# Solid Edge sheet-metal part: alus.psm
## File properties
Author: Romil
Template: iso sheet metal.psm
Last saved by: Romil
Revision: 9
Application: Solid Edge
Accuracy: 0.990
Material Thickness: 1.00 mm
Bend Radius: 1.00 mm
Relief Width: 1.00 mm
Relief Length: 0.00 mm
Neutral Factor: 0.330
Minimum Arc Length: 0.10 mm
Deviational Tolerance: 0.10 mm
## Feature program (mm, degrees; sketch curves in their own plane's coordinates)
base tab "unnamed BaseTab 1"
jog tab "JogTab_1"  OffsetDistance = 10 mm
mirror "unnamed Mirror 1" of "JogTab_1" about plane through (0, 0, 0) normal (1, 0, 0)
jog tab "unnamed JogTab 1"
flange "Flange_2"
dimple "Dimple_1"
mirror "unnamed Mirror 2" of "Dimple_1" about plane through (0, 0, 0) normal (1, 0, 0)
dimple "unnamed Dimple 1"
louver "Louver_2"  LouverDepth = 5 mm; LouverHeight = 2 mm
pattern "unnamed Pattern 1" of "Louver_2"
louver "unnamed Louver 1"
louver "unnamed Louver 2"
louver "unnamed Louver 3"
louver "unnamed Louver 4"
louver "unnamed Louver 5"
louver "unnamed Louver 6"
louver "unnamed Louver 7"
flange "Flange_3"
hem "Hem_2"
bead "unnamed Bead 1"
sketch used by "ExtrudedCutout_1" plane through (51.1585, -131.9198, -39.2063) normal (0.520259, -0.854008, 0) x-axis (0.854008, 0.520259, 0)
extrude "ExtrudedCutout_1" cut
bead "unnamed Bead 2"
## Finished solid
Body 1: solid body, 365 faces, 932 edges, 584 vertices, 9 separate solids.
  Faces by surface: plane 182, cylinder 62, swept 41, sphere 32, cone 20, torus 20, spline 8
  Edges by curve: line 582, circle 240, spline 82, curve on surface 16, ellipse 12
Bounding box of the edges (mm; curved faces can reach further): 153.576 x 205.571 x 12.250, from (-76.7881, -147.7331, -45.2063) to (76.7881, 57.8381, -32.9563).
Cylindrical faces by radius (mm): R0.002 x1, R1 x38, R1.002 x1, R2 x6, R6.25 x8, R7.25 x8
Conical faces (half-angle, radius in mm at the cone's reference point): 15 deg R0.3014 x2, 15 deg R0.6363 x2, 15 deg R1.2673 x2, 15 deg R1.6023 x2, 15 deg R12.9375 x2, 15 deg R13.9034 x2, 15 deg R14.8411 x2, 15 deg R15.807 x2, 15 deg R24.3385 x1, 15 deg R25.3044 x1, 15 deg R26.2422 x1, 15 deg R27.2081 x1
Toroidal faces (ring radius, tube radius in mm): R0.5 r1 x4, R1.6023 r1 x4, R12.9375 r1 x2, R14.0397 r1 x2, R15.0397 r1 x2, R16.142 r1 x2, R24.3385 r1 x1, R25.4408 r1 x1, R26.4408 r1 x1, R27.543 r1 x1
Spherical faces by radius (mm): R6.25 x16, R7.25 x16
Planar faces by outward normal: +x 3, +y 10, +z 33, -x 3, -y 12, -z 28, oblique 93
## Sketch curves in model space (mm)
spline (69.9628, -120.4643, -40.5603) -> (70.6542, -120.0431, -40.5603) -> (71.3456, -119.6219, -40.5603)
spline (69.5461, -120.7181, -38.5998) -> (71.3144, -119.6409, -38.329) -> (69.9628, -120.4643, -40.5603)
spline (69.9011, -120.5018, -38.6457) -> (69.7236, -120.61, -38.6227) -> (69.5461, -120.7181, -38.5998)
spline (69.4788, -120.7591, -40.9454) -> (70.946, -119.8653, -38.7796) -> (69.9011, -120.5018, -38.6457)
spline (71.3456, -119.6219, -40.9454) -> (70.4122, -120.1905, -40.9454) -> (69.4788, -120.7591, -40.9454)
spline (71.3456, -119.6219, -40.5603) -> (71.3456, -119.6219, -40.7529) -> (71.3456, -119.6219, -40.9454)
spline (68.6491, -121.2646, -37.6501) -> (68.6491, -121.2646, -39.2978) -> (68.6491, -121.2646, -40.9454)
spline (68.4268, -121.4, -37.6501) -> (68.5379, -121.3323, -37.6501) -> (68.6491, -121.2646, -37.6501)
spline (67.6139, -121.8952, -38.475) -> (68.0774, -121.6129, -38.1335) -> (68.4268, -121.4, -37.6501)
spline (67.6139, -121.8952, -38.8645) -> (67.6139, -121.8952, -38.6698) -> (67.6139, -121.8952, -38.475)
spline (68.3053, -121.474, -38.3788) -> (67.9783, -121.6732, -38.6567) -> (67.6139, -121.8952, -38.8645)
spline (68.3053, -121.474, -40.9454) -> (68.3053, -121.474, -39.6621) -> (68.3053, -121.474, -38.3788)
spline (68.6491, -121.2646, -40.9454) -> (68.4772, -121.3693, -40.9454) -> (68.3053, -121.474, -40.9454)
closed spline through (65.5247, -123.1679, -39.3262), (66.0846, -122.8269, -40.6675), (66.6383, -122.4896, -39.6153), (66.0705, -122.8354, -37.9828)
closed spline through (65.1678, -123.3854, -39.3262), (66.1581, -122.7821, -37.6533), (66.9978, -122.2705, -39.5223), (65.8508, -122.9693, -40.9685)
spline (63.415, -124.4532, -40.5603) -> (64.1064, -124.032, -40.5603) -> (64.7978, -123.6108, -40.5603)
spline (62.9983, -124.707, -38.5998) -> (64.7526, -123.6383, -38.2677) -> (63.415, -124.4532, -40.5603)
spline (63.3552, -124.4896, -38.6457) -> (63.1767, -124.5983, -38.6227) -> (62.9983, -124.707, -38.5998)
spline (62.9329, -124.7469, -40.9454) -> (64.2743, -123.9297, -39.043) -> (63.3552, -124.4896, -38.6457)
spline (64.7978, -123.6108, -40.9454) -> (63.8653, -124.1788, -40.9454) -> (62.9329, -124.7469, -40.9454)
spline (64.7978, -123.6108, -40.5603) -> (64.7978, -123.6108, -40.7529) -> (64.7978, -123.6108, -40.9454)
spline (60.9147, -125.9763, -40.9454) -> (60.7493, -126.0771, -40.9454) -> (60.584, -126.1778, -40.9454)
spline (61.6809, -125.5096, -38.5604) -> (61.2978, -125.743, -39.7529) -> (60.9147, -125.9763, -40.9454)
spline (61.3258, -125.7259, -38.5604) -> (61.5033, -125.6178, -38.5604) -> (61.6809, -125.5096, -38.5604)
spline (60.7465, -126.0788, -40.4706) -> (61.0302, -125.906, -39.5131) -> (61.3258, -125.7259, -38.5604)
spline (60.1803, -126.4237, -38.5604) -> (60.4705, -126.2469, -39.5127) -> (60.7465, -126.0788, -40.4706)
spline (59.8141, -126.6469, -38.5604) -> (59.9972, -126.5353, -38.5604) -> (60.1803, -126.4237, -38.5604)
spline (60.584, -126.1778, -40.9454) -> (60.199, -126.4123, -39.7529) -> (59.8141, -126.6469, -38.5604)
closed spline through (58.0743, -127.7067, -39.7529), (58.6698, -127.3439, -40.6675), (59.2664, -126.9805, -39.7657), (58.6698, -127.3439, -38.8383)
closed spline through (57.7174, -127.9241, -39.7529), (58.6792, -127.3382, -38.5079), (59.6227, -126.7634, -39.7914), (58.6489, -127.3567, -40.9999)
spline (56.2244, -128.8337, -40.9454) -> (56.0534, -128.9379, -40.9454) -> (55.8824, -129.042, -40.9454)
spline (56.2244, -128.8337, -40.0024) -> (56.2244, -128.8337, -40.4739) -> (56.2244, -128.8337, -40.9454)
spline (56.4636, -128.688, -39.731) -> (56.344, -128.7608, -39.8667) -> (56.2244, -128.8337, -40.0024)
spline (57.1475, -128.2713, -40.9454) -> (56.8055, -128.4797, -40.3382) -> (56.4636, -128.688, -39.731)
spline (57.5735, -128.0118, -40.9454) -> (57.3605, -128.1416, -40.9454) -> (57.1475, -128.2713, -40.9454)
spline (56.7121, -128.5366, -39.4488) -> (57.1428, -128.2742, -40.1971) -> (57.5735, -128.0118, -40.9454)
spline (57.4932, -128.0607, -38.5604) -> (57.1026, -128.2987, -39.0046) -> (56.7121, -128.5366, -39.4488)
spline (57.0466, -128.3328, -38.5604) -> (57.2699, -128.1968, -38.5604) -> (57.4932, -128.0607, -38.5604)
spline (56.2244, -128.8337, -39.5275) -> (56.6355, -128.5833, -39.044) -> (57.0466, -128.3328, -38.5604)
spline (56.2244, -128.8337, -37.6589) -> (56.2244, -128.8337, -38.5932) -> (56.2244, -128.8337, -39.5275)
spline (55.8824, -129.042, -37.6589) -> (56.0534, -128.9379, -37.6589) -> (56.2244, -128.8337, -37.6589)
spline (55.8824, -129.042, -40.9454) -> (55.8824, -129.042, -39.3022) -> (55.8824, -129.042, -37.6589)
spline (54.0399, -130.1645, -40.9454) -> (53.868, -130.2692, -40.9454) -> (53.6961, -130.3739, -40.9454)
spline (55.0079, -129.5748, -40.9454) -> (54.5491, -129.8542, -38.8539) -> (54.0399, -130.1645, -40.9454)
spline (55.3517, -129.3653, -40.9454) -> (55.1798, -129.4701, -40.9454) -> (55.0079, -129.5748, -40.9454)
spline (54.0063, -130.185, -38.8995) -> (55.3195, -129.385, -39.0302) -> (55.3517, -129.3653, -40.9454)
spline (54.0063, -130.185, -38.5604) -> (54.0063, -130.185, -38.73) -> (54.0063, -130.185, -38.8995)
spline (53.6961, -130.3739, -38.5604) -> (53.8512, -130.2794, -38.5604) -> (54.0063, -130.185, -38.5604)
spline (53.6961, -130.3739, -40.9454) -> (53.6961, -130.3739, -39.7529) -> (53.6961, -130.3739, -38.5604)
spline (52.9112, -130.8521, -39.5253) -> (52.3485, -131.1948, -38.8382) -> (51.7769, -131.5431, -39.5253)
spline (51.7769, -131.5431, -39.5253) -> (52.3441, -131.1976, -39.5253) -> (52.9112, -130.8521, -39.5253)
spline (51.7582, -131.5544, -39.8579) -> (52.2206, -131.2728, -40.6481) -> (52.9075, -130.8543, -40.1752)
spline (53.2719, -130.6323, -39.8579) -> (52.5151, -131.0934, -39.8579) -> (51.7582, -131.5544, -39.8579)
spline (53.2625, -130.638, -40.2277) -> (51.4188, -131.7612, -39.4833) -> (53.2719, -130.6323, -39.8579)
spline (52.9075, -130.8543, -40.1752) -> (53.085, -130.7462, -40.2015) -> (53.2625, -130.638, -40.2277)
spline (50.0466, -132.5972, -37.6436) -> (50.1503, -132.534, -37.8317) -> (50.254, -132.4708, -38.0199)
spline (49.6523, -132.8374, -37.6436) -> (49.8494, -132.7173, -37.6436) -> (50.0466, -132.5972, -37.6436)
spline (50.0634, -132.587, -38.2672) -> (49.8578, -132.7122, -37.9554) -> (49.6523, -132.8374, -37.6436)
spline (50.4259, -132.3661, -38.2672) -> (50.2446, -132.4765, -38.2672) -> (50.0634, -132.587, -38.2672)
spline (50.865, -132.0986, -37.6436) -> (50.6455, -132.2323, -37.9554) -> (50.4259, -132.3661, -38.2672)
spline (50.4689, -132.3399, -37.6436) -> (50.6669, -132.2193, -37.6436) -> (50.865, -132.0986, -37.6436)
spline (50.254, -132.4708, -38.0199) -> (50.3614, -132.4054, -37.8317) -> (50.4689, -132.3399, -37.6436)
spline (50.6894, -132.2056, -39.2321) -> (51.0377, -131.9934, -39.9281) -> (49.4112, -132.9842, -40.2277)
spline (51.0257, -132.0007, -39.1796) -> (50.8576, -132.1031, -39.2059) -> (50.6894, -132.2056, -39.2321)
spline (49.7532, -132.7759, -40.1752) -> (49.5555, -132.8963, -39.5323) -> (51.0257, -132.0007, -39.1796)
spline (49.4112, -132.9842, -40.2277) -> (49.5822, -132.8801, -40.2015) -> (49.7532, -132.7759, -40.1752)
spline (48.8637, -133.3178, -38.8777) -> (48.8637, -133.3178, -39.901) -> (49.2131, -133.1049, -40.5844)
spline (49.2131, -133.1049, -38.8777) -> (49.0384, -133.2114, -38.8777) -> (48.8637, -133.3178, -38.8777)
spline (49.2131, -133.1049, -38.5604) -> (49.2131, -133.1049, -38.719) -> (49.2131, -133.1049, -38.8777)
spline (48.8637, -133.3178, -38.5604) -> (49.0384, -133.2114, -38.5604) -> (49.2131, -133.1049, -38.5604)
spline (48.8637, -133.3178, -37.7289) -> (48.8637, -133.3178, -38.1446) -> (48.8637, -133.3178, -38.5604)
spline (48.5199, -133.5273, -37.9718) -> (48.6918, -133.4225, -37.8503) -> (48.8637, -133.3178, -37.7289)
spline (48.5199, -133.5273, -38.5604) -> (48.5199, -133.5273, -38.2661) -> (48.5199, -133.5273, -37.9718)
spline (48.2638, -133.6832, -38.5604) -> (48.3918, -133.6052, -38.5604) -> (48.5199, -133.5273, -38.5604)
spline (48.2638, -133.6832, -38.8777) -> (48.2638, -133.6832, -38.719) -> (48.2638, -133.6832, -38.5604)
spline (48.5199, -133.5273, -38.8777) -> (48.3918, -133.6052, -38.8777) -> (48.2638, -133.6832, -38.8777)
spline (49.2598, -133.0765, -40.9411) -> (48.5199, -133.5272, -40.2671) -> (48.5199, -133.5273, -38.8777)
spline (49.2131, -133.1049, -40.5844) -> (49.2365, -133.0907, -40.7627) -> (49.2598, -133.0765, -40.9411)
closed spline through (46.582, -134.7078, -39.7354), (47.1118, -134.385, -40.6675), (47.6891, -134.0333, -39.6786), (47.1539, -134.3594, -38.8385)
spline (46.5895, -134.7032, -40.6478) -> (46.5895, -134.7032, -40.7966) -> (46.5895, -134.7032, -40.9454)
spline (46.6157, -134.6873, -38.8273) -> (48.0371, -133.8214, -39.927) -> (46.5895, -134.7032, -40.6478)
spline (46.6157, -134.6873, -37.6589) -> (46.6157, -134.6873, -38.2431) -> (46.6157, -134.6873, -38.8273)
spline (46.2718, -134.8967, -37.6589) -> (46.4438, -134.792, -37.6589) -> (46.6157, -134.6873, -37.6589)
spline (46.2718, -134.8967, -40.9454) -> (46.2718, -134.8967, -39.3022) -> (46.2718, -134.8967, -37.6589)
spline (46.5895, -134.7032, -40.9454) -> (46.4307, -134.8, -40.9454) -> (46.2718, -134.8967, -40.9454)
spline (44.5527, -135.9441, -38.2759) -> (44.4237, -136.0226, -38.2759) -> (44.2948, -136.1012, -38.2759)
spline (45.5804, -135.3179, -37.7573) -> (45.1463, -135.5824, -38.2608) -> (44.5527, -135.9441, -38.2759)
spline (45.33, -135.4705, -37.7573) -> (45.4552, -135.3942, -37.7573) -> (45.5804, -135.3179, -37.7573)
spline (44.2948, -136.1012, -38.2759) -> (44.6748, -135.8697, -37.7662) -> (45.33, -135.4705, -37.7573)
closed spline through (44.3284, -136.0807, -39.7529), (44.9232, -135.7183, -40.6676), (45.5205, -135.3545, -39.7657), (44.9233, -135.7183, -38.8383)
closed spline through (43.9715, -136.2981, -39.7529), (44.9154, -135.7231, -38.5079), (45.8772, -135.1372, -39.7709), (44.8997, -135.7327, -40.9999)
spline (41.6899, -137.6881, -38.0199) -> (41.6899, -137.6881, -38.5648) -> (41.6899, -137.6881, -39.1096)
spline (41.6899, -137.6881, -39.1096) -> (43.1811, -136.7796, -38.5526) -> (41.6899, -137.6881, -38.0199)
spline (41.6899, -137.6881, -40.9454) -> (41.5058, -137.8002, -40.9454) -> (41.3217, -137.9123, -40.9454)
spline (41.6899, -137.6881, -39.4881) -> (41.6899, -137.6881, -40.2168) -> (41.6899, -137.6881, -40.9454)
spline (43.325, -136.692, -40.9454) -> (42.7027, -137.0711, -39.8332) -> (41.6899, -137.6881, -39.4881)
spline (43.7903, -136.4085, -40.9454) -> (43.5576, -136.5502, -40.9454) -> (43.325, -136.692, -40.9454)
spline (42.7718, -137.0289, -39.4488) -> (43.3464, -136.6789, -40.1264) -> (43.7903, -136.4085, -40.9454)
spline (41.3217, -137.9123, -37.6589) -> (43.2477, -136.739, -37.8145) -> (42.7718, -137.0289, -39.4488)
spline (41.3217, -137.9123, -40.9454) -> (41.3217, -137.9123, -39.3022) -> (41.3217, -137.9123, -37.6589)
spline (39.6399, -138.9369, -40.9454) -> (39.469, -139.041, -40.9454) -> (39.298, -139.1452, -40.9454)
spline (39.6399, -138.9369, -37.6589) -> (39.6399, -138.9369, -39.3022) -> (39.6399, -138.9369, -40.9454)
spline (39.298, -139.1452, -37.6589) -> (39.469, -139.041, -37.6589) -> (39.6399, -138.9369, -37.6589)
spline (39.298, -139.1452, -40.9454) -> (39.298, -139.1452, -39.3022) -> (39.298, -139.1452, -37.6589)
spline (38.7822, -139.4594, -40.9454) -> (38.6112, -139.5636, -40.9454) -> (38.4403, -139.6677, -40.9454)
spline (38.7822, -139.4594, -38.5604) -> (38.7822, -139.4594, -39.7529) -> (38.7822, -139.4594, -40.9454)
spline (38.4403, -139.6677, -38.5604) -> (38.6112, -139.5636, -38.5604) -> (38.7822, -139.4594, -38.5604)
spline (38.4403, -139.6677, -40.9454) -> (38.4403, -139.6677, -39.7529) -> (38.4403, -139.6677, -38.5604)
spline (38.7822, -139.4594, -38.1206) -> (38.6112, -139.5636, -38.1206) -> (38.4403, -139.6677, -38.1206)
spline (38.7822, -139.4594, -37.6589) -> (38.7822, -139.4594, -37.8897) -> (38.7822, -139.4594, -38.1206)
spline (38.4403, -139.6677, -37.6589) -> (38.6112, -139.5636, -37.6589) -> (38.7822, -139.4594, -37.6589)
spline (38.4403, -139.6677, -38.1206) -> (38.4403, -139.6677, -37.8897) -> (38.4403, -139.6677, -37.6589)
spline (35.5083, -141.4538, -40.9454) -> (35.3364, -141.5586, -40.9454) -> (35.1645, -141.6633, -40.9454)
spline (36.3717, -140.9279, -40.9454) -> (35.9764, -141.1687, -38.8544) -> (35.5083, -141.4538, -40.9454)
spline (36.7136, -140.7196, -40.9454) -> (36.5426, -140.8237, -40.9454) -> (36.3717, -140.9279, -40.9454)
spline (37.5769, -140.1936, -40.9454) -> (37.1748, -140.4386, -38.8542) -> (36.7136, -140.7196, -40.9454)
spline (37.9208, -139.9842, -40.9454) -> (37.7489, -140.0889, -40.9454) -> (37.5769, -140.1936, -40.9454)
spline (36.6613, -140.7515, -38.9214) -> (37.8976, -139.9983, -39.0297) -> (37.9208, -139.9842, -40.9454)
spline (35.4672, -141.4789, -38.893) -> (36.099, -141.094, -38.508) -> (36.6613, -140.7515, -38.9214)
spline (35.4672, -141.4789, -38.5604) -> (35.4672, -141.4789, -38.7267) -> (35.4672, -141.4789, -38.893)
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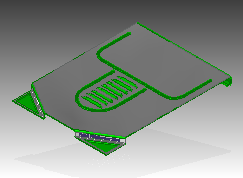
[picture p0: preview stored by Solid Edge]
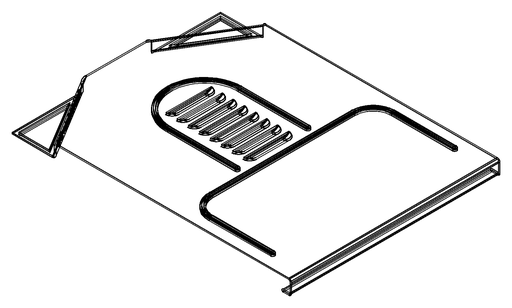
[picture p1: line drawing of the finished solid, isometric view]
